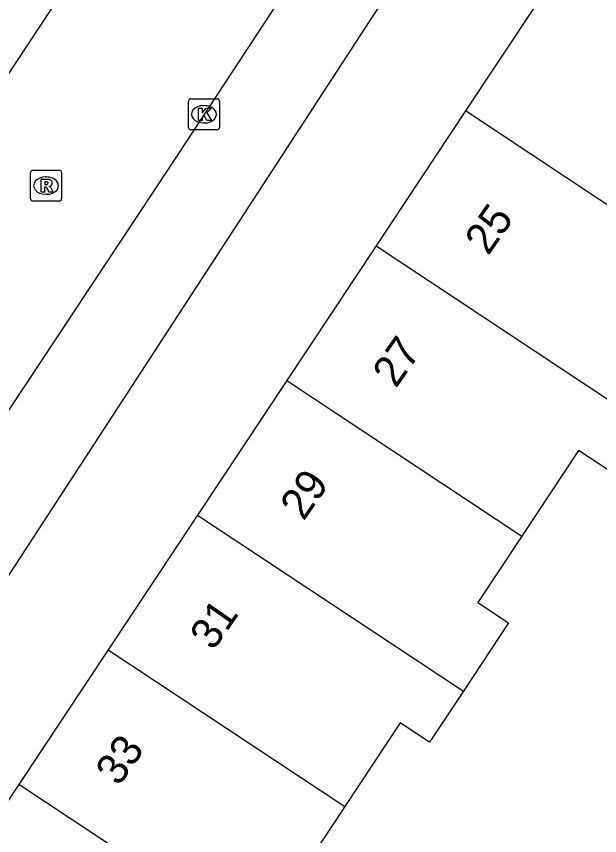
# Model space of a CAD drawing. Extents: x 159280 to 160375, y 384531 to 385872.
# Drawn here: x 160069.3 to 160088.12, y 384904.54 to 384930.99 of the extents above; entities that cross this region are included whole.
import ezdxf

# ---------------------------------------------------------------- set-up
doc = ezdxf.new("R2010")
doc.units = 0
for name, color, linetype in [('IMGEO_Kolk', 7, 'Continuous'), ('IMGEO_Pand', 7, 'Continuous'), ('IMGEO_Pand_nummerreeks', 7, 'Continuous'), ('IMGEO_Rijbaan_lokaal_open', 7, 'Continuous'), ('IMGEO_Rioolput', 7, 'Continuous'), ('IMGEO_Voetpad_open', 7, 'Continuous')]:
    doc.layers.add(name, color=color, linetype=linetype)

msp = doc.modelspace()

# ---------------------------------------------------------------- linework, layer by layer
at = {"layer": 'IMGEO_Kolk'}
for p, q in [((160074.854, 384927.4), (160074.854, 384928.252)), ((160074.929, 384928.326), (160075.781, 384928.326)), ((160075.855, 384928.252), (160075.855, 384927.4)), ((160075.342, 384928.106), (160075.367, 384928.106)), ((160075.365, 384927.546), (160075.34, 384927.546)), ((160075.781, 384927.326), (160074.929, 384927.326))]:
    msp.add_line(p, q, dxfattribs=at)
for points in [[(160074.854, 384927.4), (160074.854, 384928.252)], [(160074.929, 384928.326), (160075.781, 384928.326)], [(160075.855, 384928.252), (160075.855, 384927.4)], [(160075.175, 384928.026), (160075.298, 384928.026), (160075.298, 384927.875), (160075.428, 384928.026), (160075.592, 384928.026), (160075.446, 384927.875), (160075.599, 384927.626), (160075.447, 384927.626), (160075.362, 384927.79), (160075.298, 384927.723), (160075.298, 384927.626), (160075.175, 384927.626), (160075.175, 384928.026)], [(160075.781, 384927.326), (160074.929, 384927.326)]]:
    msp.add_lwpolyline(points, dxfattribs=at)
for centre, start, end in [((160074.931, 384928.25), 91.552, 178.448), ((160074.931, 384928.25), 91.552, 178.448), ((160075.779, 384928.25), 1.552, 88.448), ((160075.779, 384928.25), 1.552, 88.448), ((160074.931, 384927.402), 181.552, 268.448), ((160074.931, 384927.402), 181.552, 268.448), ((160075.779, 384927.402), 271.552, 358.448), ((160075.779, 384927.402), 271.552, 358.448)]:
    msp.add_arc(centre, 0.0765, start, end, dxfattribs=at)
for centre, major_axis, ratio, start_param, end_param in [((160075.341, 384927.826), (-0.387, 0.002), 0.722429, 4.712389, 7.853982), ((160075.366, 384927.826), (-0.39, 0.002), 0.717154, 1.570796, 4.712389)]:
    msp.add_ellipse(centre, major_axis=major_axis, ratio=ratio, start_param=start_param, end_param=end_param, dxfattribs=at)
at = {"layer": 'IMGEO_Pand'}
for points in [[(160089.553, 384936.617), (160083.797, 384927.933)], [(160083.797, 384927.933), (160080.913, 384923.581)], [(160091.595, 384923.335), (160091.333, 384922.938), (160083.797, 384927.933)], [(160080.913, 384923.581), (160078.031, 384919.233)], [(160080.913, 384923.581), (160089.485, 384917.899)], [(160078.031, 384919.233), (160075.148, 384914.883)], [(160078.031, 384919.233), (160085.613, 384914.207)], [(160089.485, 384917.899), (160088.437, 384916.315), (160087.443, 384916.973), (160085.613, 384914.207)], [(160075.148, 384914.883), (160072.266, 384910.536)], [(160075.148, 384914.883), (160083.726, 384909.197)], [(160085.613, 384914.207), (160084.191, 384912.058), (160085.185, 384911.401), (160083.726, 384909.197)], [(160072.266, 384910.536), (160069.384, 384906.187)], [(160072.266, 384910.536), (160079.901, 384905.474)], [(160083.726, 384909.197), (160082.638, 384907.553), (160081.691, 384908.18), (160079.901, 384905.474)], [(160069.384, 384906.187), (160066.501, 384901.838)], [(160078.049, 384900.443), (160069.384, 384906.187)], [(160079.901, 384905.474), (160078.413, 384903.226), (160079.433, 384902.551), (160078.049, 384900.443)]]:
    msp.add_lwpolyline(points, dxfattribs=at)
at = {"layer": 'IMGEO_Rijbaan_lokaal_open'}
for points in [[(160076.665, 384940.228), (160073.371, 384935.228), (160070.408, 384931.21), (160063.509, 384920.762)], [(160081.07, 384936.53), (160074.237, 384926.124), (160068.515, 384917.483)]]:
    msp.add_lwpolyline(points, dxfattribs=at)
at = {"layer": 'IMGEO_Rioolput'}
for p, q in [((160069.757, 384925.096), (160069.757, 384925.948)), ((160069.832, 384926.022), (160070.684, 384926.022)), ((160070.245, 384925.802), (160070.27, 384925.802)), ((160070.758, 384925.948), (160070.758, 384925.096)), ((160070.268, 384925.242), (160070.243, 384925.242)), ((160070.684, 384925.022), (160069.832, 384925.022))]:
    msp.add_line(p, q, dxfattribs=at)
for points in [[(160069.757, 384925.096), (160069.757, 384925.948)], [(160069.832, 384926.022), (160070.684, 384926.022)], [(160070.758, 384925.948), (160070.758, 384925.096)], [(160070.346, 384925.72), (160070.094, 384925.722), (160070.094, 384925.322)], [(160070.272, 384925.641), (160070.218, 384925.641), (160070.218, 384925.56)], [(160070.218, 384925.56), (160070.27, 384925.56)], [(160070.094, 384925.322), (160070.218, 384925.322), (160070.218, 384925.484), (160070.229, 384925.484)], [(160070.276, 384925.455), (160070.347, 384925.322), (160070.487, 384925.322), (160070.422, 384925.448)], [(160070.684, 384925.022), (160069.832, 384925.022)]]:
    msp.add_lwpolyline(points, dxfattribs=at)
for centre, radius, start, end in [((160069.834, 384925.946), 0.0765, 91.552, 178.448), ((160069.834, 384925.946), 0.0765, 91.552, 178.448), ((160070.682, 384925.946), 0.0765, 1.552, 88.448), ((160070.682, 384925.946), 0.0765, 1.552, 88.448), ((160070.254, 384925.749), 0.19, 274.7715, 282.9687), ((160070.278, 384925.545), 0.0964, 77.0061, 93.1865), ((160070.292, 384925.602), 0.0378, 276.6634, 79.6772), ((160070.345, 384925.61), 0.109, 350.3612, 89.416), ((160070.343, 384925.61), 0.112, 277.5842, 350.9817), ((160070.228, 384925.431), 0.0533, 26.0293, 88.6989), ((160070.327, 384925.395), 0.108, 29.5134, 73.7905), ((160069.834, 384925.098), 0.0765, 181.552, 268.448), ((160069.834, 384925.098), 0.0765, 181.552, 268.448), ((160070.682, 384925.098), 0.0765, 271.552, 358.448), ((160070.682, 384925.098), 0.0765, 271.552, 358.448)]:
    msp.add_arc(centre, radius, start, end, dxfattribs=at)
for centre, major_axis, ratio, start_param, end_param in [((160070.244, 384925.522), (-0.387, 0.002), 0.722429, 4.712389, 7.853982), ((160070.269, 384925.522), (-0.39, 0.002), 0.717154, 1.570796, 4.712389)]:
    msp.add_ellipse(centre, major_axis=major_axis, ratio=ratio, start_param=start_param, end_param=end_param, dxfattribs=at)
at = {"layer": 'IMGEO_Voetpad_open'}
msp.add_lwpolyline([(160054.6, 384890.738), (160083.589, 384935.277)], dxfattribs=at)

# ---------------------------------------------------------------- texts
at = {"layer": 'IMGEO_Pand_nummerreeks'}
for s, rotation, p in [('25', 55.1816, (160084.528, 384923.239)), ('27', 55.183, (160081.549, 384918.954)), ('29', 55.183, (160078.569, 384914.67)), ('31', 55.183, (160075.654, 384910.478)), ('33', 55.183, (160072.61, 384906.101))]:
    msp.add_text(s, height=1, rotation=rotation, dxfattribs=at).set_placement(p)

doc.saveas('drawing.dxf')
